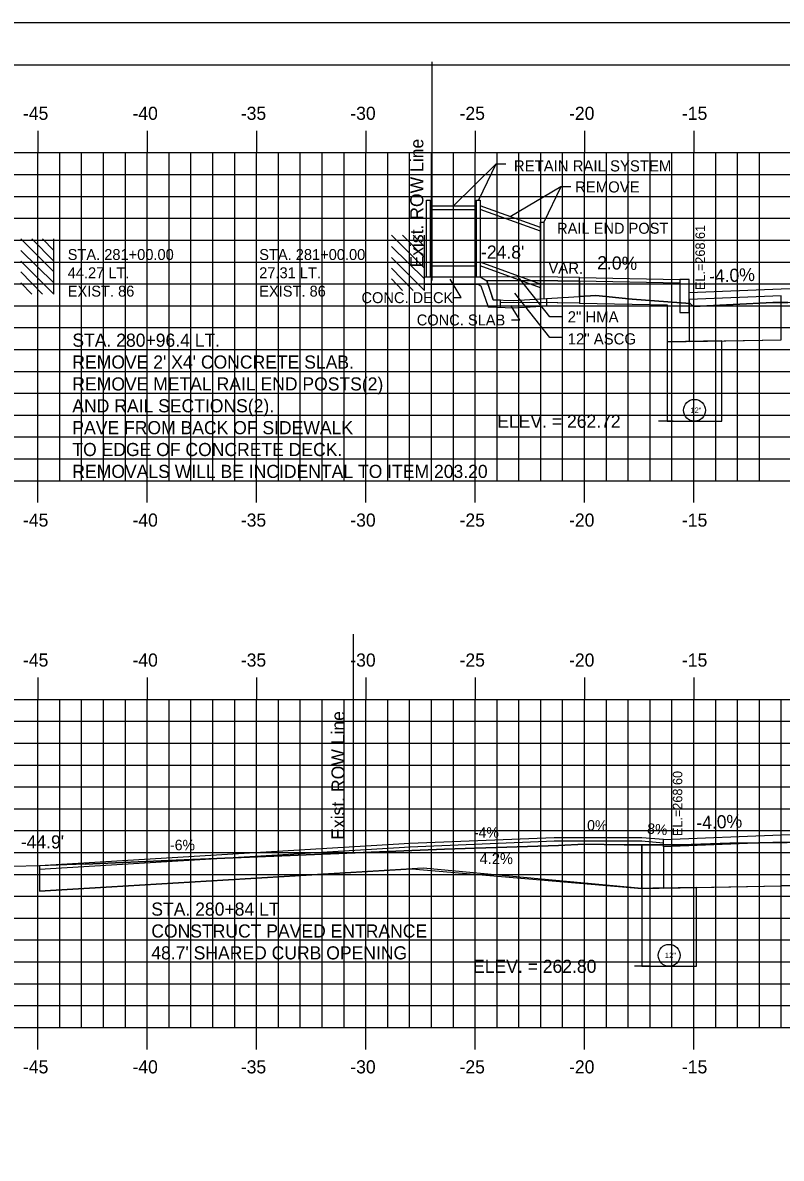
# Model space of a CAD drawing. Extents: x 855344 to 855514, y 366268 to 366378.
# Drawn here: x 855381.4 to 855416.1, y 366326.3 to 366378.2 of the extents above; entities that cross this region are included whole.
import ezdxf

# ---------------------------------------------------------------- set-up
doc = ezdxf.new("R2010")
doc.units = 0
for name, color, linetype in [('ANNOTATION', 7, 'Continuous'), ('BORDER', 7, 'Continuous'), ('D_Curb_Type_1_Lt', 7, 'Continuous'), ('D_Roadway_Drive_Gravel_LT', 7, 'Continuous'), ('D_Roadway_Drive_SubGrade', 7, 'Continuous'), ('D_Roadway_Edge_Shoulder', 7, 'Continuous'), ('D_Roadway_FinishedGrade', 7, 'Continuous'), ('D_Roadway_Sidewalks_Paved', 7, 'Continuous'), ('D_Roadway_SubGrade', 7, 'Continuous'), ('D_Text_Monospaced', 7, 'Continuous'), ('D_Text_Standard', 7, 'Continuous'), ('E_ROW_Line', 7, 'Continuous'), ('H_V ANNOTATION', 7, 'Continuous'), ('JUNK COM EXC', 7, 'Continuous'), ('JUNK FILL', 7, 'Continuous'), ('junk strct exc', 7, 'Continuous'), ('MAJOR', 7, 'Continuous'), ('MINOR', 7, 'Continuous'), ('PATTERNING', 7, 'Continuous'), ('PDRAIN', 7, 'Continuous'), ('PLOT BOUNDARY', 7, 'Continuous'), ('S_Buildings', 7, 'Continuous'), ('S_Fencing_Other', 7, 'Continuous'), ('S_Roadway_Centerline', 7, 'Continuous'), ('TEXT', 7, 'Continuous')]:
    doc.layers.add(name, color=color, linetype=linetype)

msp = doc.modelspace()

# ---------------------------------------------------------------- linework, layer by layer
at = {"layer": 'ANNOTATION'}
for p, q in [((855403.057, 366371.707), (855401.111, 366369.807)), ((855406.032, 366370.679), (855403.716, 366369.308))]:
    msp.add_line(p, q, dxfattribs=at)
for points in [[(855403.505, 366371.707), (855403.057, 366371.707), (855402.267, 366370.057)], [(855406.479, 366370.679), (855406.032, 366370.679), (855405.256, 366369.059)], [(855406.11, 366364.736), (855405.529, 366364.736), (855404.14, 366366.476)], [(855401.096, 366365.62), (855401.473, 366365.62), (855400.963, 366366.444)], [(855406.11, 366363.785), (855405.529, 366363.785), (855403.916, 366365.805)], [(855403.772, 366364.596), (855404.148, 366364.596), (855403.742, 366365.253)]]:
    msp.add_lwpolyline(points, dxfattribs=at)
at = {"layer": 'BORDER'}
msp.add_line((855512.11, 366376.236), (855352.11, 366376.236), dxfattribs=at)
at = {"layer": 'D_Curb_Type_1_Lt'}
msp.add_lwpolyline([(855411.475, 366366.431), (855411.475, 366364.931), (855411.891, 366364.931), (855411.891, 366366.431)], close=True, dxfattribs=at)
at = {"layer": 'D_Roadway_Drive_Gravel_LT'}
for p, q in [((855399.118, 366340.649), (855382.187, 366339.633)), ((855405.728, 366340.914), (855399.118, 366340.649)), ((855405.734, 366340.747), (855399.125, 366340.483)), ((855409.728, 366340.914), (855405.728, 366340.914)), ((855409.728, 366340.747), (855405.728, 366340.747)), ((855410.728, 366340.666), (855409.715, 366340.748)), ((855410.728, 366340.834), (855409.728, 366340.914)), ((855410.728, 366340.501), (855410.728, 366340.834)), ((855399.128, 366340.483), (855382.187, 366339.466)), ((855399.728, 366339.517), (855382.187, 366338.465))]:
    msp.add_line(p, q, dxfattribs=at)
at = {"layer": 'D_Roadway_Drive_SubGrade'}
for p, q in [((855382.187, 366339.633), (855382.187, 366338.467)), ((855409.728, 366338.595), (855399.728, 366339.517)), ((855410.728, 366338.615), (855409.728, 366338.595))]:
    msp.add_line(p, q, dxfattribs=at)
at = {"layer": 'D_Roadway_Edge_Shoulder'}
for points in [[(855411.891, 366365.848), (855416.11, 366366.016), (855427.11, 366366.236), (855438.11, 366366.016), (855442.107, 366365.856)], [(855410.728, 366340.834), (855416.11, 366341.049), (855427.11, 366341.268), (855438.11, 366341.048), (855442.107, 366340.888)]]:
    msp.add_lwpolyline(points, dxfattribs=at)
at = {"layer": 'D_Roadway_FinishedGrade'}
for p, q in [((855405.886, 366366.376), (855402.611, 366366.389)), ((855406.883, 366366.356), (855405.883, 366366.376)), ((855405.882, 366365.376), (855403.272, 366365.386)), ((855406.863, 366365.356), (855405.863, 366365.376))]:
    msp.add_line(p, q, dxfattribs=at)
for points in [[(855405.886, 366366.542), (855402.343, 366366.557)], [(855406.886, 366366.522), (855405.886, 366366.542)]]:
    msp.add_lwpolyline(points, dxfattribs=at)
at = {"layer": 'D_Roadway_Sidewalks_Paved'}
msp.add_lwpolyline([(855406.886, 366366.522), (855411.475, 366366.431), (855411.475, 366366.264), (855406.886, 366366.356)], close=True, dxfattribs=at)
at = {"layer": 'D_Roadway_SubGrade'}
msp.add_line((855411.891, 366363.599), (855410.891, 366363.579), dxfattribs=at)
msp.add_lwpolyline([(855406.886, 366366.356), (855406.886, 366365.355), (855410.891, 366365.275), (855410.891, 366363.579)], dxfattribs=at)
for points in [[(855416.11, 366365.683), (855411.891, 366365.515), (855411.891, 366363.599), (855416.11, 366363.683)], [(855416.11, 366340.716), (855410.728, 366340.501), (855410.728, 366338.608), (855416.11, 366338.716)], [(855416.11, 366338.716), (855416.11, 366340.716), (855427.11, 366340.936), (855438.11, 366340.716), (855438.11, 366338.716), (855427.11, 366338.936)]]:
    msp.add_lwpolyline(points, close=True, dxfattribs=at)
at = {"layer": 'D_Text_Standard'}
for points in [[(855410.891, 366359.956), (855411.171, 366359.956), (855410.491, 366359.956)], [(855409.728, 366335.034), (855410.081, 366335.034), (855409.401, 366335.034)]]:
    msp.add_lwpolyline(points, dxfattribs=at)
at = {"layer": 'E_ROW_Line'}
for p, q in [((855400.139, 366366.385), (855400.139, 366376.385)), ((855396.537, 366340.217), (855396.537, 366350.217))]:
    msp.add_line(p, q, dxfattribs=at)
at = {"layer": 'JUNK COM EXC'}
for points in [[(855416.406, 366365.387), (855415.725, 366365.379), (855412.088, 366365.206), (855411.944, 366365.344), (855409.284, 366365.542), (855407.633, 366365.705), (855406.886, 366365.659), (855406.886, 366365.355), (855410.891, 366365.275), (855410.891, 366363.579), (855416.11, 366363.683)], [(855409.728, 366340.586), (855408.927, 366340.586), (855407.101, 366340.624), (855405.927, 366340.564), (855400.711, 366340.39), (855388.432, 366339.882), (855384.275, 366339.699), (855382.187, 366339.633), (855382.187, 366338.465), (855399.209, 366339.486), (855409.728, 366338.595), (855409.728, 366340.586)]]:
    msp.add_lwpolyline(points, dxfattribs=at)
msp.add_lwpolyline([(855409.728, 366340.586), (855409.728, 366338.595), (855416.11, 366338.716), (855427.11, 366338.936), (855438.11, 366338.716), (855443.107, 366338.615), (855448.002, 366338.517), (855455.456, 366339.926), (855455.456, 366341.093), (855450.133, 366341.025), (855443.985, 366340.92), (855443.109, 366341.055), (855442.502, 366341.148), (855438.987, 366341.077), (855437.99, 366341.069), (855437.021, 366341.068), (855427.216, 366341.257), (855420.216, 366340.964), (855416.384, 366340.7), (855413.757, 366340.668), (855411.541, 366340.585)], close=True, dxfattribs=at)
at = {"layer": 'JUNK FILL'}
msp.add_lwpolyline([(855406.886, 366365.659), (855406.886, 366366.356), (855406.886, 366366.522), (855405.886, 366366.542), (855402.343, 366366.557), (855402.643, 366366.369), (855402.923, 366365.554), (855402.938, 366365.51), (855403.859, 366365.474), (855406.886, 366365.659)], dxfattribs=at)
at = {"layer": 'junk strct exc'}
for points in [[(855410.891, 366363.579), (855410.891, 366359.956), (855413.391, 366359.956), (855413.391, 366363.629)], [(855409.728, 366338.595), (855409.728, 366335.034), (855412.228, 366335.034), (855412.228, 366338.638)]]:
    msp.add_lwpolyline(points, close=True, dxfattribs=at)
at = {"layer": 'MAJOR'}
for p, q in [((855382.11, 366373.238), (855382.11, 366372.236)), ((855387.11, 366373.238), (855387.11, 366372.236)), ((855392.11, 366373.238), (855392.11, 366372.236)), ((855397.11, 366373.238), (855397.11, 366372.236)), ((855402.11, 366373.238), (855402.11, 366372.236)), ((855407.11, 366373.238), (855407.11, 366372.236)), ((855412.11, 366373.238), (855412.11, 366372.236)), ((855357.11, 366372.236), (855497.11, 366372.236)), ((855357.11, 366372.236), (855497.11, 366372.236)), ((855382.11, 366357.236), (855382.11, 366372.236)), ((855387.11, 366357.236), (855387.11, 366372.236)), ((855392.11, 366357.236), (855392.11, 366372.236)), ((855397.11, 366357.236), (855397.11, 366372.236)), ((855402.11, 366357.236), (855402.11, 366372.236)), ((855407.11, 366357.236), (855407.11, 366372.236)), ((855412.11, 366357.236), (855412.11, 366372.236)), ((855357.11, 366367.236), (855497.11, 366367.236)), ((855357.11, 366362.236), (855497.11, 366362.236)), ((855357.11, 366357.236), (855497.11, 366357.236)), ((855357.11, 366357.236), (855497.11, 366357.236)), ((855382.11, 366356.234), (855382.11, 366357.236)), ((855387.11, 366356.234), (855387.11, 366357.236)), ((855392.11, 366356.234), (855392.11, 366357.236)), ((855397.11, 366356.234), (855397.11, 366357.236)), ((855402.11, 366356.234), (855402.11, 366357.236)), ((855407.11, 366356.234), (855407.11, 366357.236)), ((855412.11, 366356.234), (855412.11, 366357.236)), ((855382.11, 366348.238), (855382.11, 366347.236)), ((855387.11, 366348.238), (855387.11, 366347.236)), ((855392.11, 366348.238), (855392.11, 366347.236)), ((855397.11, 366348.238), (855397.11, 366347.236)), ((855402.11, 366348.238), (855402.11, 366347.236)), ((855407.11, 366348.238), (855407.11, 366347.236)), ((855412.11, 366348.238), (855412.11, 366347.236)), ((855357.11, 366347.236), (855497.11, 366347.236)), ((855357.11, 366347.236), (855497.11, 366347.236)), ((855382.11, 366332.236), (855382.11, 366347.236)), ((855387.11, 366332.236), (855387.11, 366347.236)), ((855392.11, 366332.236), (855392.11, 366347.236)), ((855397.11, 366332.236), (855397.11, 366347.236)), ((855402.11, 366332.236), (855402.11, 366347.236)), ((855407.11, 366332.236), (855407.11, 366347.236)), ((855412.11, 366332.236), (855412.11, 366347.236)), ((855357.11, 366342.236), (855497.11, 366342.236)), ((855357.11, 366337.236), (855497.11, 366337.236)), ((855357.11, 366332.236), (855497.11, 366332.236)), ((855357.11, 366332.236), (855497.11, 366332.236)), ((855382.11, 366331.234), (855382.11, 366332.236)), ((855387.11, 366331.234), (855387.11, 366332.236)), ((855392.11, 366331.234), (855392.11, 366332.236)), ((855397.11, 366331.234), (855397.11, 366332.236)), ((855402.11, 366331.234), (855402.11, 366332.236)), ((855407.11, 366331.234), (855407.11, 366332.236)), ((855412.11, 366331.234), (855412.11, 366332.236))]:
    msp.add_line(p, q, dxfattribs=at)
at = {"layer": 'MINOR'}
for p, q in [((855383.11, 366357.236), (855383.11, 366372.236)), ((855384.11, 366357.236), (855384.11, 366372.236)), ((855385.11, 366357.236), (855385.11, 366372.236)), ((855386.11, 366357.236), (855386.11, 366372.236)), ((855388.11, 366357.236), (855388.11, 366372.236)), ((855389.11, 366357.236), (855389.11, 366372.236)), ((855390.11, 366357.236), (855390.11, 366372.236)), ((855391.11, 366357.236), (855391.11, 366372.236)), ((855393.11, 366357.236), (855393.11, 366372.236)), ((855394.11, 366357.236), (855394.11, 366372.236)), ((855395.11, 366357.236), (855395.11, 366372.236)), ((855396.11, 366357.236), (855396.11, 366372.236)), ((855398.11, 366357.236), (855398.11, 366372.236)), ((855399.11, 366357.236), (855399.11, 366372.236)), ((855400.11, 366357.236), (855400.11, 366372.236)), ((855401.11, 366357.236), (855401.11, 366372.236)), ((855403.11, 366357.236), (855403.11, 366372.236)), ((855404.11, 366357.236), (855404.11, 366372.236)), ((855405.11, 366357.236), (855405.11, 366372.236)), ((855406.11, 366357.236), (855406.11, 366372.236)), ((855408.11, 366357.236), (855408.11, 366372.236)), ((855409.11, 366357.236), (855409.11, 366372.236)), ((855410.11, 366357.236), (855410.11, 366372.236)), ((855411.11, 366357.236), (855411.11, 366372.236)), ((855413.11, 366357.236), (855413.11, 366372.236)), ((855414.11, 366357.236), (855414.11, 366372.236)), ((855415.11, 366357.236), (855415.11, 366372.236)), ((855357.11, 366371.236), (855497.11, 366371.236)), ((855357.11, 366370.236), (855497.11, 366370.236)), ((855357.11, 366369.236), (855497.11, 366369.236)), ((855357.11, 366368.236), (855497.11, 366368.236)), ((855357.11, 366366.236), (855497.11, 366366.236)), ((855357.11, 366365.236), (855497.11, 366365.236)), ((855357.11, 366364.236), (855497.11, 366364.236)), ((855357.11, 366363.236), (855497.11, 366363.236)), ((855357.11, 366361.236), (855497.11, 366361.236)), ((855357.11, 366360.236), (855497.11, 366360.236)), ((855357.11, 366359.236), (855497.11, 366359.236)), ((855357.11, 366358.236), (855497.11, 366358.236)), ((855383.11, 366332.236), (855383.11, 366347.236)), ((855384.11, 366332.236), (855384.11, 366347.236)), ((855385.11, 366332.236), (855385.11, 366347.236)), ((855386.11, 366332.236), (855386.11, 366347.236)), ((855388.11, 366332.236), (855388.11, 366347.236)), ((855389.11, 366332.236), (855389.11, 366347.236)), ((855390.11, 366332.236), (855390.11, 366347.236)), ((855391.11, 366332.236), (855391.11, 366347.236)), ((855393.11, 366332.236), (855393.11, 366347.236)), ((855394.11, 366332.236), (855394.11, 366347.236)), ((855395.11, 366332.236), (855395.11, 366347.236)), ((855396.11, 366332.236), (855396.11, 366347.236)), ((855398.11, 366332.236), (855398.11, 366347.236)), ((855399.11, 366332.236), (855399.11, 366347.236)), ((855400.11, 366332.236), (855400.11, 366347.236)), ((855401.11, 366332.236), (855401.11, 366347.236)), ((855403.11, 366332.236), (855403.11, 366347.236)), ((855404.11, 366332.236), (855404.11, 366347.236)), ((855405.11, 366332.236), (855405.11, 366347.236)), ((855406.11, 366332.236), (855406.11, 366347.236)), ((855408.11, 366332.236), (855408.11, 366347.236)), ((855409.11, 366332.236), (855409.11, 366347.236)), ((855410.11, 366332.236), (855410.11, 366347.236)), ((855411.11, 366332.236), (855411.11, 366347.236)), ((855413.11, 366332.236), (855413.11, 366347.236)), ((855414.11, 366332.236), (855414.11, 366347.236)), ((855415.11, 366332.236), (855415.11, 366347.236)), ((855416.11, 366332.236), (855416.11, 366347.236)), ((855357.11, 366346.236), (855497.11, 366346.236)), ((855357.11, 366345.236), (855497.11, 366345.236)), ((855357.11, 366344.236), (855497.11, 366344.236)), ((855357.11, 366343.236), (855497.11, 366343.236)), ((855357.11, 366341.236), (855497.11, 366341.236)), ((855357.11, 366340.236), (855497.11, 366340.236)), ((855357.11, 366339.236), (855497.11, 366339.236)), ((855357.11, 366338.236), (855497.11, 366338.236)), ((855357.11, 366336.236), (855497.11, 366336.236)), ((855357.11, 366335.236), (855497.11, 366335.236)), ((855357.11, 366334.236), (855497.11, 366334.236)), ((855357.11, 366333.236), (855497.11, 366333.236))]:
    msp.add_line(p, q, dxfattribs=at)
at = {"layer": 'PATTERNING'}
msp.add_lwpolyline([(855402.611, 366366.389), (855405.886, 366366.376), (855406.883, 366366.356), (855406.886, 366365.355), (855405.882, 366365.376), (855403.272, 366365.386), (855403.272, 366365.497), (855402.938, 366365.51), (855402.79, 366365.94), (855402.643, 366366.369), (855402.611, 366366.389)], close=True, dxfattribs=at)
at = {"layer": 'PDRAIN'}
for points in [[(855410.891, 366363.579), (855410.891, 366359.956), (855413.391, 366359.956), (855413.391, 366363.629)], [(855409.728, 366338.595), (855409.728, 366335.034), (855412.228, 366335.034), (855412.228, 366338.638)]]:
    msp.add_lwpolyline(points, dxfattribs=at)
for centre in [(855412.141, 366360.456), (855410.978, 366335.534)]:
    msp.add_circle(centre, 0.5, dxfattribs=at)
at = {"layer": 'PLOT BOUNDARY'}
msp.add_lwpolyline([(855344.016, 366268.177), (855514.016, 366268.177), (855514.016, 366378.177), (855344.016, 366378.177)], close=True, dxfattribs=at)
at = {"layer": 'S_Buildings'}
for p, q in [((855382.843, 366366.782), (855381.333, 366368.291)), ((855382.843, 366367.274), (855381.826, 366368.291)), ((855382.843, 366367.766), (855382.318, 366368.291)), ((855382.843, 366365.764), (855382.843, 366368.291)), ((855399.796, 366366.955), (855398.287, 366368.465)), ((855399.796, 366367.448), (855398.779, 366368.465)), ((855399.796, 366367.94), (855399.271, 366368.465)), ((855399.796, 366365.938), (855399.796, 366368.465)), ((855382.843, 366366.289), (855381.333, 366367.766)), ((855399.796, 366366.463), (855398.287, 366367.94)), ((855382.843, 366365.764), (855381.333, 366367.274)), ((855399.796, 366365.938), (855398.287, 366367.448)), ((855382.318, 366365.764), (855381.333, 366366.782)), ((855399.271, 366365.938), (855398.287, 366366.955)), ((855398.779, 366365.938), (855398.287, 366366.463)), ((855381.826, 366365.764), (855381.333, 366366.289))]:
    msp.add_line(p, q, dxfattribs=at)
at = {"layer": 'S_Fencing_Other'}
for p, q in [((855400.046, 366369.807), (855402.176, 366369.807)), ((855400.046, 366369.64), (855402.176, 366369.64)), ((855405.089, 366368.809), (855402.343, 366369.807)), ((855405.089, 366368.643), (855402.343, 366369.64)), ((855400.046, 366367.224), (855402.176, 366367.224)), ((855405.089, 366366.226), (855402.343, 366367.224)), ((855405.089, 366366.059), (855402.343, 366367.057))]:
    msp.add_line(p, q, dxfattribs=at)
for points in [[(855399.88, 366366.557), (855399.88, 366370.057), (855400.046, 366370.057), (855400.046, 366366.557)], [(855402.176, 366366.557), (855402.176, 366370.057), (855402.343, 366370.057), (855402.343, 366366.557)], [(855405.089, 366365.559), (855405.089, 366369.059), (855405.256, 366369.059), (855405.256, 366365.559)], [(855400.046, 366367.057), (855402.176, 366367.057)]]:
    msp.add_lwpolyline(points, dxfattribs=at)
at = {"layer": 'S_Roadway_Centerline'}
for p, q in [((855403.272, 366365.164), (855403.272, 366365.497)), ((855405.381, 366365.233), (855405.381, 366365.567))]:
    msp.add_line(p, q, dxfattribs=at)
for points in [[(855399.796, 366366.557), (855402.343, 366366.557), (855402.643, 366366.369), (855402.938, 366365.51), (855403.859, 366365.474), (855407.633, 366365.705), (855409.284, 366365.542), (855411.944, 366365.344), (855412.088, 366365.206), (855415.725, 366365.379), (855416.406, 366365.387), (855426.605, 366366.089), (855427.071, 366366.108), (855427.725, 366366.096), (855437.92, 366366.106), (855441.388, 366366.135), (855442.313, 366366.102), (855445.427, 366366.167), (855450.069, 366366.134), (855463.667, 366366.46)], [(855399.796, 366366.224), (855402.247, 366366.223), (855402.366, 366366.149), (855402.697, 366365.187), (855403.862, 366365.14), (855405.381, 366365.233)], [(855384.275, 366339.699), (855388.432, 366339.882), (855400.711, 366340.39), (855405.927, 366340.564), (855407.101, 366340.624), (855408.927, 366340.586), (855411.541, 366340.585), (855413.757, 366340.668), (855416.384, 366340.7), (855420.216, 366340.964), (855427.216, 366341.257), (855437.021, 366341.068), (855437.99, 366341.069), (855438.987, 366341.077), (855442.502, 366341.148), (855443.985, 366340.92), (855449.999, 366341.018), (855450.133, 366341.025), (855450.439, 366341.026), (855468.024, 366341.26), (855473.254, 366341.359), (855474.777, 366341.358), (855474.83, 366341.346)], [(855384.275, 366339.699), (855382.187, 366339.633), (855380.943, 366339.594)]]:
    msp.add_lwpolyline(points, dxfattribs=at)

# ---------------------------------------------------------------- texts
at = {"layer": 'ANNOTATION'}
for s, rotation, p in [('2.0%', 358.8542, (855407.684, 366366.907)), ('-4.0%', 2.2906, (855412.816, 366366.285)), ('-4.0%', 2.2906, (855412.235, 366341.295))]:
    msp.add_text(s, height=0.6, rotation=rotation, dxfattribs=at).set_placement(p)
for s, p in [('STA. 280+84 LT', (855387.296, 366337.348)), ('CONSTRUCT PAVED ENTRANCE', (855387.296, 366336.348)), ("48.7' SHARED CURB OPENING", (855387.296, 366335.348))]:
    msp.add_text(s, height=0.6, dxfattribs=at).set_placement(p)
at = {"layer": 'D_Roadway_Drive_Gravel_LT'}
for s, rotation, p in [('0%', 358.8078, (855407.224, 366341.242)), ('8%', 355.4261, (855409.958, 366341.101))]:
    msp.add_text(s, height=0.48, rotation=rotation, dxfattribs=at).set_placement(p)
for s, p in [(' -4%', (855401.874, 366340.914)), (' -6%', (855387.975, 366340.338))]:
    msp.add_text(s, height=0.48, dxfattribs=at).set_placement(p)
at = {"layer": 'D_Text_Monospaced'}
for s, height, p in [('RAIL END POST', 0.49998, (855405.856, 366368.528)), ('STA. 281+00.00', 0.49998, (855383.472, 366367.328)), ('STA. 281+00.00', 0.49998, (855392.231, 366367.328)), ('44.27 LT.', 0.5, (855383.472, 366366.494)), ('27.31 LT.', 0.5, (855392.231, 366366.494)), ('EXIST. 86', 0.5, (855383.472, 366365.654)), ('EXIST. 86', 0.5, (855392.231, 366365.654)), ('CONC. DECK', 0.5, (855396.909, 366365.355)), ('CONC. SLAB', 0.5, (855399.436, 366364.335))]:
    msp.add_text(s, height=height, dxfattribs=at).set_placement(p)
at = {"layer": 'D_Text_Standard'}
for s, height, p in [('RETAIN RAIL SYSTEM', 0.51, (855403.88, 366371.376)), ('REMOVE', 0.51, (855406.674, 366370.414)), ("-24.8'", 0.6, (855402.376, 366367.39)), ('2" HMA', 0.51, (855406.341, 366364.474)), ('STA. 280+96.4 LT.', 0.6, (855383.685, 366363.362)), ('12" ASCG', 0.51, (855406.341, 366363.467)), ("REMOVE 2' X4' CONCRETE SLAB.", 0.6, (855383.685, 366362.362)), ('REMOVE METAL RAIL END POSTS(2)', 0.6, (855383.685, 366361.362)), ('AND RAIL SECTIONS(2).', 0.6, (855383.685, 366360.362)), ('ELEV. = 262.72', 0.6, (855403.118, 366359.656)), ('PAVE FROM BACK OF SIDEWALK', 0.6, (855383.685, 366359.362)), ('TO EDGE OF CONCRETE DECK.', 0.6, (855383.685, 366358.362)), ('REMOVALS WILL BE INCIDENTAL TO ITEM 203.20', 0.6, (855383.685, 366357.362)), ("-44.9'", 0.6, (855381.326, 366340.42)), ('ELEV. = 262.80', 0.6, (855402.011, 366334.734))]:
    msp.add_text(s, height=height, dxfattribs=at).set_placement(p)
for s, height, rotation, p in [(' EL.=268.61', 0.4335, 90, (855412.618, 366365.79)), ('VAR.', 0.51, 359.0684, (855405.453, 366366.717)), (' EL.=268.60', 0.4335, 90, (855411.581, 366340.823))]:
    msp.add_text(s, height=height, rotation=rotation, dxfattribs=at).set_placement(p)
at = {"layer": 'E_ROW_Line'}
for p in [(855399.738, 366366.985), (855396.137, 366340.817)]:
    msp.add_text('Exist. ROW Line', height=0.6, rotation=90, dxfattribs=at).set_placement(p)
at = {"layer": 'H_V ANNOTATION'}
for s, p in [('-45', (855381.427, 366373.736)), ('-40', (855386.435, 366373.736)), ('-35', (855391.39, 366373.736)), ('-30', (855396.398, 366373.736)), ('-25', (855401.395, 366373.736)), ('-20', (855406.403, 366373.736)), ('-15', (855411.566, 366373.736)), ('-45', (855381.427, 366355.136)), ('-40', (855386.435, 366355.136)), ('-35', (855391.39, 366355.136)), ('-30', (855396.398, 366355.136)), ('-25', (855401.395, 366355.136)), ('-20', (855406.403, 366355.136)), ('-15', (855411.566, 366355.136)), ('-45', (855381.427, 366348.736)), ('-40', (855386.435, 366348.736)), ('-35', (855391.39, 366348.736)), ('-30', (855396.398, 366348.736)), ('-25', (855401.395, 366348.736)), ('-20', (855406.403, 366348.736)), ('-15', (855411.566, 366348.736)), ('-45', (855381.427, 366330.136)), ('-40', (855386.435, 366330.136)), ('-35', (855391.39, 366330.136)), ('-30', (855396.398, 366330.136)), ('-25', (855401.395, 366330.136)), ('-20', (855406.403, 366330.136)), ('-15', (855411.566, 366330.136))]:
    msp.add_text(s, height=0.6, dxfattribs=at).set_placement(p)
at = {"layer": 'PDRAIN'}
for p in [(855411.951, 366360.332), (855410.787, 366335.41)]:
    msp.add_text('12"', height=0.25, dxfattribs=at).set_placement(p)
at = {"layer": 'TEXT'}
msp.add_text('4.2%', height=0.5, dxfattribs=at).set_placement((855402.311, 366339.704))

doc.saveas('drawing.dxf')
